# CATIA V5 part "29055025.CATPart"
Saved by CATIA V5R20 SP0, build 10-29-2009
Part number: 29055025
Definition: NONE
Nomenclature: 29055025
Source: Unknown
Description: 29055025
Bounding box of the stored display mesh (mm): x -12.5 to 44.548, y -41.5 to 76.048, z -31.5 to 31.5
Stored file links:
  C:\Users\Utente\Desktop\IO LAVORO\3D X SITO CF\X SITO\PLASTICA\RF1\29055025.CATPart
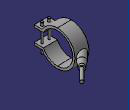
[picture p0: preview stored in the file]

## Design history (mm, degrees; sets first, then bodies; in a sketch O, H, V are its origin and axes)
Body1 "29055025" (main body)
  Solid1: solid without history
